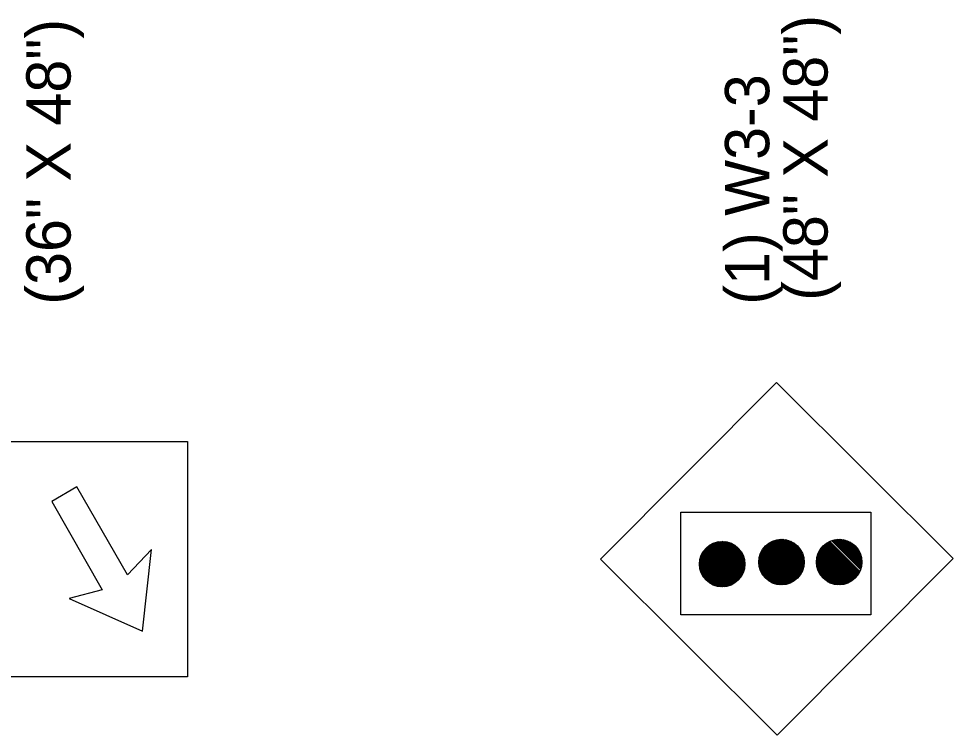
# Model space of a CAD drawing. Extents: x 1806907 to 1812607, y 675071 to 676228.
# Drawn here: x 1809741 to 1809867.6, y 675421.4 to 675518.5 of the extents above; entities that cross this region are included whole.
import ezdxf

# ---------------------------------------------------------------- set-up
doc = ezdxf.new("R2010")
doc.units = 0
doc.layers.add('Default', color=7, linetype='Continuous')

msp = doc.modelspace()

# ---------------------------------------------------------------- linework, layer by layer
at = {"layer": 'Default'}
for p, q in [((1809843.64, 675469.23), (1809819.8, 675445.29)), ((1809843.64, 675469.23), (1809867.59, 675445.37)), ((1809839, 675443.14), (1809834.82, 675447.32)), ((1809839.07, 675443.26), (1809834.94, 675447.39)), ((1809839.13, 675443.39), (1809835.07, 675447.45)), ((1809839.18, 675443.53), (1809835.21, 675447.5)), ((1809839.23, 675443.67), (1809835.35, 675447.55)), ((1809839.27, 675443.81), (1809835.49, 675447.59)), ((1809839.31, 675443.97), (1809835.65, 675447.63)), ((1809839.34, 675444.13), (1809835.81, 675447.66)), ((1809839.36, 675444.29), (1809835.98, 675447.68)), ((1809839.37, 675444.47), (1809836.15, 675447.69)), ((1809839.38, 675444.66), (1809836.34, 675447.7)), ((1809839.37, 675444.86), (1809836.54, 675447.69)), ((1809839.34, 675445.07), (1809836.75, 675447.66)), ((1809839.3, 675445.31), (1809836.99, 675447.62)), ((1809839.23, 675445.57), (1809837.25, 675447.54)), ((1809839.11, 675445.88), (1809837.56, 675447.43)), ((1809846.73, 675442.96), (1809842.39, 675447.3)), ((1809846.81, 675443.07), (1809842.5, 675447.38)), ((1809846.89, 675443.18), (1809842.61, 675447.46)), ((1809846.96, 675443.3), (1809842.73, 675447.53)), ((1809847.03, 675443.42), (1809842.85, 675447.6)), ((1809847.1, 675443.54), (1809842.97, 675447.67)), ((1809847.16, 675443.67), (1809843.1, 675447.73)), ((1809847.21, 675443.81), (1809843.24, 675447.78)), ((1809847.26, 675443.95), (1809843.38, 675447.83)), ((1809847.3, 675444.1), (1809843.53, 675447.87)), ((1809847.34, 675444.25), (1809843.68, 675447.91)), ((1809847.37, 675444.41), (1809843.84, 675447.94)), ((1809847.39, 675444.58), (1809844.01, 675447.96)), ((1809847.41, 675444.75), (1809844.18, 675447.98)), ((1809847.41, 675444.94), (1809844.37, 675447.98)), ((1809847.4, 675445.14), (1809844.57, 675447.97)), ((1809847.37, 675445.35), (1809844.78, 675447.94)), ((1809847.33, 675445.59), (1809845.02, 675447.9)), ((1809847.26, 675445.85), (1809845.28, 675447.83)), ((1809847.14, 675446.16), (1809845.59, 675447.71)), ((1809846.91, 675446.58), (1809846.01, 675447.48)), ((1809854.57, 675443.01), (1809850.24, 675447.34)), ((1809854.65, 675443.12), (1809850.35, 675447.42)), ((1809854.72, 675443.23), (1809850.46, 675447.49)), ((1809854.8, 675443.35), (1809850.58, 675447.57)), ((1809854.86, 675443.47), (1809850.71, 675447.63)), ((1809854.93, 675443.6), (1809850.83, 675447.7)), ((1809855.04, 675443.87), (1809851.1, 675447.8)), ((1809855.08, 675444.01), (1809851.25, 675447.85)), ((1809855.12, 675444.16), (1809851.39, 675447.89)), ((1809855.16, 675444.32), (1809851.55, 675447.93)), ((1809855.18, 675444.48), (1809851.71, 675447.95)), ((1809855.2, 675444.65), (1809851.89, 675447.97)), ((1809855.21, 675444.84), (1809852.07, 675447.98)), ((1809855.21, 675445.03), (1809852.26, 675447.98)), ((1809855.19, 675445.23), (1809852.46, 675447.96)), ((1809855.16, 675445.46), (1809852.69, 675447.93)), ((1809855.1, 675445.7), (1809852.93, 675447.87)), ((1809855.01, 675445.98), (1809853.21, 675447.78)), ((1809854.86, 675446.32), (1809853.56, 675447.63)), ((1809837.77, 675441.9), (1809833.58, 675446.09)), ((1809837.89, 675441.97), (1809833.65, 675446.21)), ((1809838.01, 675442.05), (1809833.73, 675446.32)), ((1809838.12, 675442.12), (1809833.81, 675446.44)), ((1809838.22, 675442.21), (1809833.89, 675446.54)), ((1809838.33, 675442.29), (1809833.97, 675446.65)), ((1809838.43, 675442.38), (1809834.06, 675446.75)), ((1809838.52, 675442.48), (1809834.16, 675446.84)), ((1809838.61, 675442.58), (1809834.26, 675446.93)), ((1809838.7, 675442.68), (1809834.36, 675447.02)), ((1809838.78, 675442.79), (1809834.47, 675447.1)), ((1809838.86, 675442.9), (1809834.58, 675447.18)), ((1809838.93, 675443.02), (1809834.7, 675447.25)), ((1809838.88, 675446.3), (1809837.98, 675447.2)), ((1809845.55, 675442.06), (1809841.49, 675446.12)), ((1809845.68, 675442.12), (1809841.55, 675446.25)), ((1809845.8, 675442.19), (1809841.62, 675446.37)), ((1809845.92, 675442.26), (1809841.69, 675446.49)), ((1809846.04, 675442.33), (1809841.76, 675446.61)), ((1809846.15, 675442.41), (1809841.84, 675446.72)), ((1809846.26, 675442.49), (1809841.92, 675446.83)), ((1809846.36, 675442.58), (1809842.01, 675446.93)), ((1809846.46, 675442.67), (1809842.1, 675447.03)), ((1809846.55, 675442.76), (1809842.19, 675447.12)), ((1809846.64, 675442.86), (1809842.29, 675447.21)), ((1809853.27, 675442.03), (1809849.26, 675446.04)), ((1809853.4, 675442.09), (1809849.32, 675446.17)), ((1809853.53, 675442.15), (1809849.38, 675446.3)), ((1809853.66, 675442.22), (1809849.45, 675446.42)), ((1809853.77, 675442.29), (1809849.52, 675446.54)), ((1809853.89, 675442.36), (1809849.59, 675446.66)), ((1809854, 675442.44), (1809849.67, 675446.77)), ((1809854.1, 675442.53), (1809849.76, 675446.87)), ((1809854.2, 675442.62), (1809849.85, 675446.97)), ((1809854.3, 675442.71), (1809849.94, 675447.07)), ((1809854.39, 675442.8), (1809850.04, 675447.16)), ((1809854.48, 675442.91), (1809850.14, 675447.25)), ((1809854.45, 675446.93), (1809854.16, 675447.22)), ((1809819.8, 675445.29), (1809843.73, 675421.43)), ((1809836.61, 675441.54), (1809833.22, 675444.93)), ((1809836.78, 675441.57), (1809833.25, 675445.1)), ((1809836.94, 675441.6), (1809833.28, 675445.26)), ((1809837.09, 675441.63), (1809833.31, 675445.41)), ((1809837.24, 675441.68), (1809833.36, 675445.56)), ((1809837.38, 675441.72), (1809833.41, 675445.7)), ((1809837.51, 675441.78), (1809833.46, 675445.83)), ((1809837.64, 675441.84), (1809833.52, 675445.96)), ((1809844.47, 675441.81), (1809841.24, 675445.04)), ((1809844.28, 675441.81), (1809841.24, 675444.85)), ((1809844.64, 675441.83), (1809841.26, 675445.21)), ((1809844.81, 675441.85), (1809841.28, 675445.38)), ((1809844.97, 675441.88), (1809841.31, 675445.54)), ((1809845.12, 675441.91), (1809841.34, 675445.69)), ((1809845.27, 675441.96), (1809841.39, 675445.84)), ((1809845.41, 675442.01), (1809841.44, 675445.98)), ((1809867.59, 675445.37), (1809843.73, 675421.43)), ((1809852.17, 675441.81), (1809849.04, 675444.93)), ((1809852.35, 675441.82), (1809849.05, 675445.12)), ((1809852.52, 675441.83), (1809849.07, 675445.29)), ((1809852.68, 675441.86), (1809849.09, 675445.45)), ((1809852.84, 675441.89), (1809849.12, 675445.61)), ((1809852.99, 675441.93), (1809849.16, 675445.76)), ((1809853.13, 675441.98), (1809849.21, 675445.9)), ((1809836.43, 675441.53), (1809833.21, 675444.75)), ((1809836.25, 675441.53), (1809833.21, 675444.57)), ((1809836.05, 675441.54), (1809833.22, 675444.37)), ((1809835.83, 675441.56), (1809833.24, 675444.15)), ((1809835.6, 675441.61), (1809833.29, 675443.92)), ((1809835.34, 675441.68), (1809833.36, 675443.66)), ((1809844.08, 675441.82), (1809841.25, 675444.65)), ((1809843.87, 675441.84), (1809841.27, 675444.44)), ((1809843.63, 675441.89), (1809841.32, 675444.2)), ((1809843.37, 675441.96), (1809841.39, 675443.94)), ((1809843.06, 675442.08), (1809841.51, 675443.63)), ((1809851.97, 675441.81), (1809849.04, 675444.74)), ((1809851.76, 675441.83), (1809849.06, 675444.53)), ((1809851.54, 675441.87), (1809849.1, 675444.31)), ((1809851.29, 675441.92), (1809849.16, 675444.06)), ((1809851.01, 675442.02), (1809849.25, 675443.78)), ((1809835.03, 675441.8), (1809833.48, 675443.35)), ((1809834.61, 675442.02), (1809833.71, 675442.93)), ((1809842.64, 675442.31), (1809841.74, 675443.21)), ((1809850.65, 675442.18), (1809849.41, 675443.42))]:
    msp.add_line(p, q, dxfattribs=at)
for points in [[(1809716.1, 675461.22), (1809763.9, 675461.22), (1809763.9, 675429.35), (1809716.1, 675429.35)], [(1809745.53, 675453.08), (1809752.35, 675441.14), (1809747.89, 675439.94), (1809757.81, 675435.52), (1809759.01, 675446.61), (1809755.78, 675443.16), (1809748.92, 675455.06)], [(1809830.68, 675437.72), (1809830.68, 675451.66), (1809856.41, 675451.66), (1809856.41, 675437.72)]]:
    msp.add_lwpolyline(points, close=True, dxfattribs=at)
for centre in [(1809836.29, 675444.61), (1809844.32, 675444.89), (1809852.13, 675444.89)]:
    msp.add_circle(centre, 3.08, dxfattribs=at)

# ---------------------------------------------------------------- texts
for s, p in [('(48" X 48")', (1809850.57, 675480.28)), ('(36" X 48")', (1809748.07, 675479.75)), ('(1) W3-3', (1809842.67, 675479.75))]:
    msp.add_text(s, height=6, rotation=90, dxfattribs=at).set_placement(p)

doc.saveas('drawing.dxf')
